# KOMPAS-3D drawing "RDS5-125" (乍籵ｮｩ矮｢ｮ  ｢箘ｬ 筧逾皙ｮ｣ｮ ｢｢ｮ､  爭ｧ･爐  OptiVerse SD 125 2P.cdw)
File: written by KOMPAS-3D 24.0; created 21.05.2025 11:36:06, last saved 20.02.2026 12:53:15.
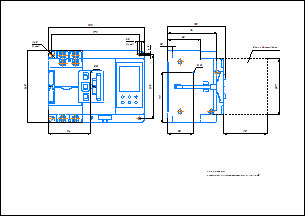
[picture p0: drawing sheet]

Document properties: Утвердил: Строгонов; Автор: keaz-admin; Проверил: Дорошев; Форматы листов документа: A2; Полное имя файла: D:\Проекты\OptiVerse SD\OptiVerse SD\OptiVerse SD 125 2P\КД\ГЖИК.648446.001 ГЧ Устройство автоматического ввода резерва OptiVerse SD 125 2P (без рамки).cdw; Масса: 2.7; Т. контр.: Пашков А.Е.; Наименование: Устройство автоматического ввода резерва OptiVerse SD 125 2P / Габаритный чертеж; Н. контр.: Гаврикова; Количество листов документа: 1; Разработал: Сулейманова

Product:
- Body: Тело 3
    Масса: 0.000001
- Component [assembly]: RDS5-125.STEP  | qty 1  | Масса: 13.010188; source file: ..\3D\Сборка 125 2Р.a3d
- Body: Тело 2
    Масса: 0.000005
- Part/product: RDS5-125
    Масса: 13.010193
    Форматы листов документа: A2

Views: Проекционный вид 2, Вид 1
Referenced files in C:\Users\user\Desktop\: GRAPHIC.LYT
Referenced files in D:\Проекты\OptiVerse SD\OptiVerse SD\OptiVerse SD 125 2P\КД\: ГЖИК.648446.001 СБ Устройство автоматического ввода резерва OptiVerse SD 125 2P.cdw
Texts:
  Устройство автоматического
  ввода резерва OptiVerse SD 125 2P
  Габаритный чертеж
  ГЖИК.648446.001ГЧ
  ГЖИК.648446.001ГЧ-
  Сулейманова
  Дорошев
  ГЖИК.648446.001
  АО "КЭАЗ"
  Строгонов
  Гаврикова
  Пашков А.Е.
  Без внутренней рамки.
Dimensions and other numbers on the sheet: 1:1; 0; 1; 2; 2,7

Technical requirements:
  Ц.М. - центр масс.
  Отклонение координат от центра масс не более 10 %.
